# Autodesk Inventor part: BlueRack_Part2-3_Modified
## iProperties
Shininess: 64.0
Length Units: 11272
Angle Units: 11279
Time Units: 11290
Mass Units: 11286
Length Display Precision: 3
Angle Display Precision: 2
Compacted: True
Part Number: BlueRack_Part2-3_Modified
Document SubType Name: Modeling
Created: 2004-12
Designer: John Blackburn
Material: Steel, Mild
Manufacturer: Standard
Standards Organization: Custom
Density: 0.0
Volumn: 0.0
Area: 0.0
PropertySet Name: Model Information
Control State: 0
Master: False
Checked Out: False
Author: John Blackburn
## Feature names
1. Extrusion1
2. Hole3
3. Rectangular Pattern3
4. Hole4
5. Rectangular Pattern4
6. Hole5
